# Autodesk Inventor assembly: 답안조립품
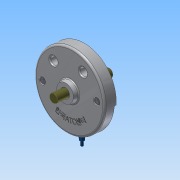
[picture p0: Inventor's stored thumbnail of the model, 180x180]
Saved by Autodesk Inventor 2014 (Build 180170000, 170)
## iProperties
Created: 2015-06
Part Number: 답안조립품
Document SubType Name: Assembly
Designer: Administrator
Author: Administrator
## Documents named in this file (9)
- C:\Documents and Settings\Administrator\바탕 화면\450631V1014\답안조립품.iam
- C:\Documents and Settings\Administrator\바탕 화면\450631V1014\1-본체.ipt
- C:\Documents and Settings\Administrator\바탕 화면\450631V1014\베어링62_22.ipt
- C:\Documents and Settings\Administrator\바탕 화면\450631V1014\덮개.ipt
- C:\Documents and Settings\Administrator\바탕 화면\450631V1014\축.ipt
- C:\Documents and Settings\Administrator\바탕 화면\450631V1014\멈춤링.ipt
- C:\Documents and Settings\Administrator\바탕 화면\450631V1014\슬라이더2.ipt
- C:\Documents and Settings\Administrator\바탕 화면\450631V1014\슬라이더.ipt
- C:\Documents and Settings\Administrator\바탕 화면\450631V1014\M10x35.ipt
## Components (7 placed, 4 different names)
1. 1-본체:1
2. KS B 2023 62/22 - 22 x 50 x 14:1
3. KS B 2023 62/22 - 22 x 50 x 14:2
4. KS B 1336 22 x 1.2:1
5. KS B 1336 22 x 1.2:2
6. KS B 1003 - 미터 M 10 x 35:1
7. KS B 1003 - 미터 M 10 x 35:2
